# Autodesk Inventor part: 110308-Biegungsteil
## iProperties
Created: 2011-03
Part Number: 110308-Biegungsteil
Document SubType Name: Sheet Metal
Designer: Schulung
Density: 1 g/cm^3
Author: Schulung
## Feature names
1. Extrusion1
2. Chamfer1
